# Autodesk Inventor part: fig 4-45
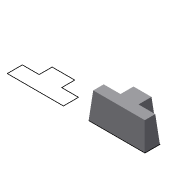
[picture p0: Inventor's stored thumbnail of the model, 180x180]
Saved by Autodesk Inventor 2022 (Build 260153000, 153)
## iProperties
Created: 2004-05
Part Number: fig 4-45
Document SubType Name: Modeling
Designer: CADCIM Technologies
Manufacturer: Standard
Standards Organization: Custom
Density: 1 g/cm^3
Material: Generic
Appearance: Default
Author: CADCIM Technologies
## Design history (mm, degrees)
sketch "Sketch1"
  geometry: L1 (31.783, 34.561)-(31.783, 22.933); L2 (31.783, 22.933)-(16.796, 22.933); L3 (16.796, 22.933)-(16.796, 9.496); L4 (16.796, 9.496)-(66.925, 9.496); L5 (66.925, 9.496)-(66.925, 22.933); L6 (66.925, 22.933)-(51.938, 22.933); L7 (51.938, 22.933)-(51.938, 34.561); L8 (51.938, 34.561)-(31.783, 34.561); L9 (-41.013, 34.561)-(-41.013, 22.933); L10 (-41.013, 22.933)-(-56, 22.933); L11 (-56, 22.933)-(-56, 9.496); L12 (-56, 9.496)-(-5.871, 9.496); L13 (-5.871, 9.496)-(-5.871, 22.933); L14 (-5.871, 22.933)-(-20.858, 22.933); L15 (-20.858, 22.933)-(-20.858, 34.561); L16 (-20.858, 34.561)-(-41.013, 34.561)
  constraints: 32 end point, 10 parallel, 4 equal length, 2 collinear, 2 perpendicular, 2 vertical
extrude "Extrusion1" new body sketch "Sketch1" distance "d0" = 23.25; taper "d1" = -5 deg
body "Solid1"
